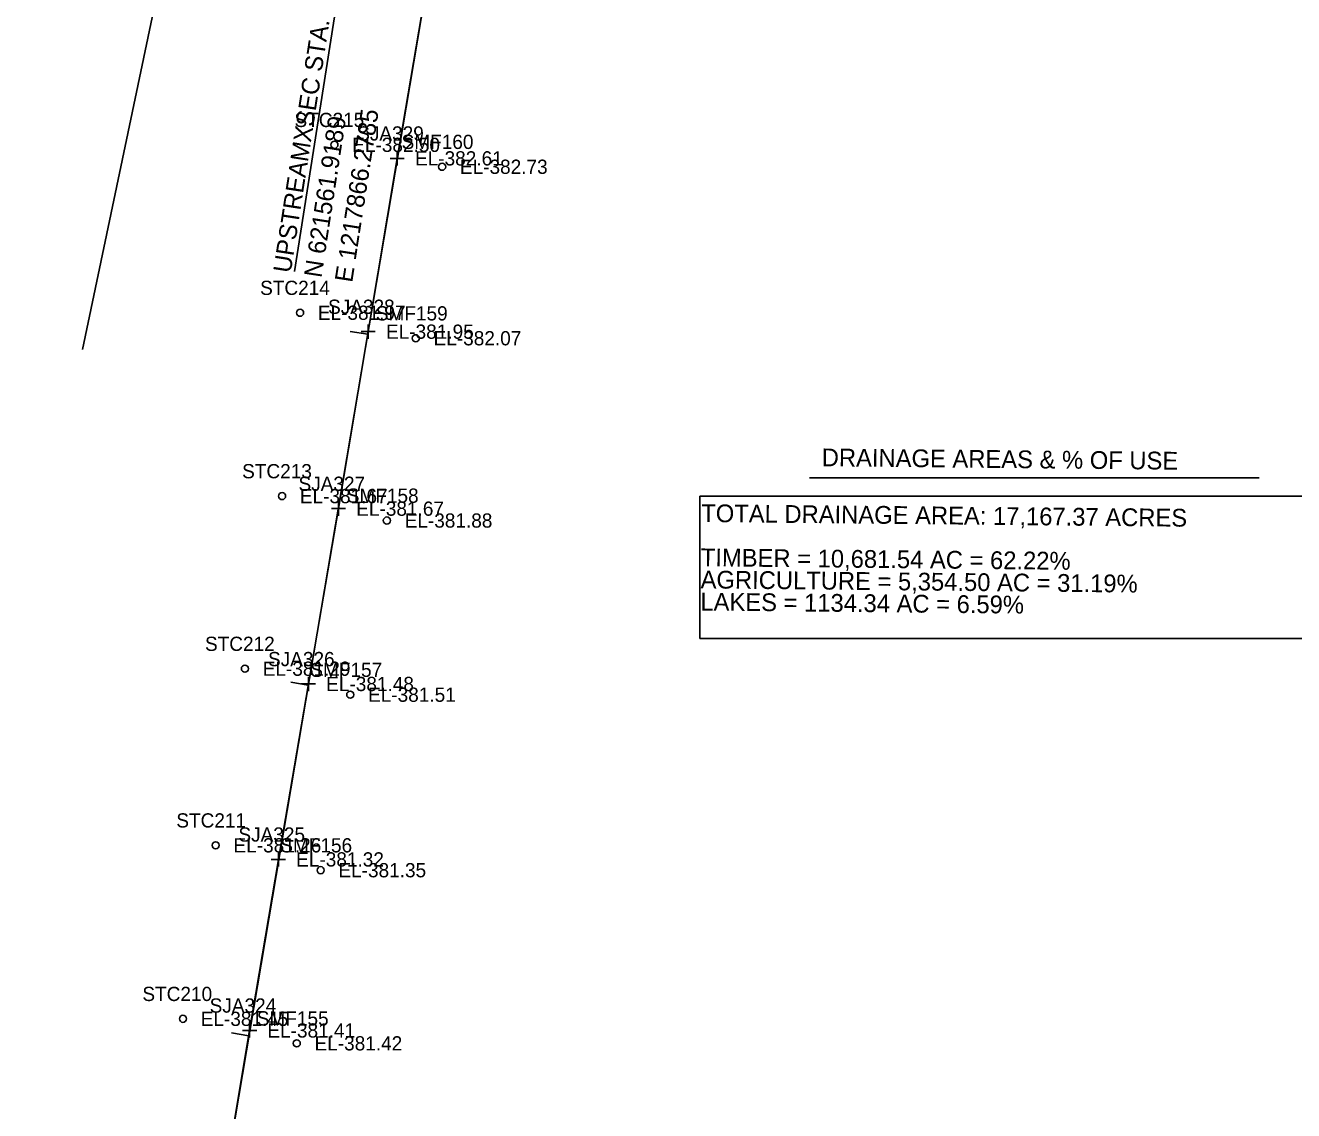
# Model space of a CAD drawing. Extents: x 1189978 to 1314812, y 571533 to 629339.
# Drawn here: x 1217758.6 to 1218115.4, y 621182.5 to 621487.6 of the extents above; entities that cross this region are included whole.
import ezdxf

# ---------------------------------------------------------------- set-up
doc = ezdxf.new("R2010")
doc.units = 0
for name, color, linetype in [('SURVEY - DRAINAGE - Area Shapes Text', 7, 'Continuous'), ('SURVEY - DRAINAGE - Bridge Hydraulic Data - Points - Elevations', 7, 'Continuous'), ('SURVEY - DRAINAGE - Bridge Hydraulic Data - Points - Numbers', 7, 'Continuous'), ('SURVEY - DRAINAGE - Bridge Hydraulic Data with Text', 7, 'Continuous'), ('SURVEY - DTM - Breaklines', 7, 'Continuous'), ('SURVEY - DTM - Spot Points - Elevations', 7, 'Continuous'), ('SURVEY - DTM - Spot Points - Locators', 7, 'Continuous'), ('SURVEY - DTM - Spot Points - Point Numbers', 7, 'Continuous')]:
    doc.layers.add(name, color=color, linetype=linetype)

msp = doc.modelspace()

# ---------------------------------------------------------------- linework, layer by layer
at = {"layer": 'SURVEY - DRAINAGE - Area Shapes Text'}
for p, q in [((1218105.72, 621360.4), (1217979.18, 621360.4)), ((1217948.4, 621355.24), (1218141.41, 621355.24)), ((1217948.4, 621355.24), (1217948.4, 621315.24)), ((1217948.4, 621315.24), (1218141.41, 621315.24))]:
    msp.add_line(p, q, dxfattribs=at)
at = {"layer": 'SURVEY - DRAINAGE - Bridge Hydraulic Data with Text'}
for p, q in [((1217654.48, 620217.59), (1218104.66, 622874.85)), ((1217654.48, 620217.59), (1218104.66, 622874.85)), ((1217654.48, 620217.59), (1218104.66, 622874.85)), ((1217774.74, 621396.44), (1217805.16, 621541.53)), ((1217854.93, 621400.73), (1217850, 621401.56)), ((1217838.22, 621302.13), (1217833.29, 621302.97)), ((1217821.52, 621203.54), (1217816.59, 621204.37))]:
    msp.add_line(p, q, dxfattribs=at)
msp.add_lwpolyline([(1217866.28, 621561.92), (1217853.48, 621540.24), (1217834.35, 621418.36)], dxfattribs=at)
at = {"layer": 'SURVEY - DTM - Breaklines'}
for p, q in [((1217863.24, 621452.2), (1217863.24, 621448.2)), ((1217865.24, 621450.2), (1217861.24, 621450.2)), ((1217855.08, 621403.48), (1217855.08, 621399.48)), ((1217857.08, 621401.48), (1217853.08, 621401.48)), ((1217846.71, 621353.72), (1217846.71, 621349.72)), ((1217848.71, 621351.72), (1217844.71, 621351.72)), ((1217840.25, 621302.43), (1217836.25, 621302.43)), ((1217838.25, 621304.43), (1217838.25, 621300.43)), ((1217831.81, 621253.11), (1217827.81, 621253.11)), ((1217829.81, 621255.11), (1217829.81, 621251.11)), ((1217821.71, 621207.02), (1217821.71, 621203.02)), ((1217823.71, 621205.02), (1217819.71, 621205.02))]:
    msp.add_line(p, q, dxfattribs=at)
msp.add_lwpolyline([(1217813.24, 621154.6), (1217821.71, 621205.02), (1217829.81, 621253.11), (1217838.25, 621302.43), (1217846.71, 621351.72), (1217855.08, 621401.48), (1217863.24, 621450.2), (1217871.68, 621499.81), (1217880.02, 621548.86)], dxfattribs=at)
at = {"layer": 'SURVEY - DTM - Spot Points - Locators'}
for centre in [(1217845.58, 621454.01), (1217875.88, 621447.84), (1217835.91, 621406.8), (1217868.47, 621399.63), (1217830.85, 621355.25), (1217860.33, 621348.38), (1217820.4, 621306.72), (1217850.03, 621299.41), (1217812.18, 621257.07), (1217841.69, 621250.07), (1217802.96, 621208.29), (1217834.97, 621201.4)]:
    msp.add_circle(centre, 1, dxfattribs=at)

# ---------------------------------------------------------------- texts
at = {"layer": 'SURVEY - DRAINAGE - Area Shapes Text'}
for s, p in [('DRAINAGE AREAS & % OF USE', (1217982.65, 621363.64)), ('TOTAL DRAINAGE AREA: 17,167.37 ACRES', (1217948.75, 621347.96)), ('TIMBER = 10,681.54 AC = 62.22%', (1217948.63, 621335.53)), ('AGRICULTURE = 5,354.50 AC = 31.19% ', (1217948.57, 621329.31)), ('LAKES = 1134.34 AC = 6.59%', (1217948.51, 621323.09))]:
    msp.add_text(s, height=4.998, rotation=359.4489, dxfattribs=at).set_placement(p)
at = {"layer": 'SURVEY - DRAINAGE - Bridge Hydraulic Data - Points - Elevations'}
for s, p in [('EL-382.61', (1217868.24, 621448.2)), ('EL-381.95', (1217860.08, 621399.48)), ('EL-381.67', (1217851.71, 621349.72)), ('EL-381.48', (1217843.25, 621300.43)), ('EL-381.32', (1217834.81, 621251.11)), ('EL-381.41', (1217826.71, 621203.02))]:
    msp.add_text(s, height=4, dxfattribs=at).set_placement(p)
at = {"layer": 'SURVEY - DRAINAGE - Bridge Hydraulic Data - Points - Numbers'}
for s, p in [('SJA329', (1217851.98, 621455.2)), ('SJA328', (1217843.79, 621406.48)), ('SJA327', (1217835.47, 621356.72)), ('SJA326', (1217826.9, 621307.43)), ('SJA325', (1217818.57, 621258.11)), ('SJA324', (1217810.47, 621210.02))]:
    msp.add_text(s, height=4, dxfattribs=at).set_placement(p)
at = {"layer": 'SURVEY - DRAINAGE - Bridge Hydraulic Data with Text'}
for s, p in [('UPSTREAMXSEC STA. 11+38.99', (1217833.27, 621417.8)), ('E 1217866.2785', (1217850.57, 621415.13)), ('N 621561.9189', (1217841.92, 621416.46))]:
    msp.add_text(s, height=5, rotation=81.2249, dxfattribs=at).set_placement(p)
at = {"layer": 'SURVEY - DTM - Spot Points - Elevations'}
for s, p in [('EL-382.50', (1217850.58, 621452.01)), ('EL-382.73', (1217880.88, 621445.84)), ('EL-381.97', (1217840.91, 621404.8)), ('EL-382.07', (1217873.47, 621397.63)), ('EL-381.67', (1217835.85, 621353.25)), ('EL-381.88', (1217865.33, 621346.38)), ('EL-381.29', (1217825.4, 621304.72)), ('EL-381.51', (1217855.03, 621297.41)), ('EL-381.26', (1217817.18, 621255.07)), ('EL-381.35', (1217846.69, 621248.07)), ('EL-381.45', (1217807.96, 621206.29)), ('EL-381.42', (1217839.97, 621199.4))]:
    msp.add_text(s, height=4, dxfattribs=at).set_placement(p)
at = {"layer": 'SURVEY - DTM - Spot Points - Point Numbers'}
for s, p in [('STC215', (1217834.34, 621459.01)), ('SMF160', (1217864.47, 621452.84)), ('STC214', (1217824.67, 621411.8)), ('SMF159', (1217857.22, 621404.63)), ('STC213', (1217819.61, 621360.25)), ('SMF158', (1217849.05, 621353.38)), ('STC212', (1217809.16, 621311.72)), ('SMF157', (1217838.79, 621304.41)), ('STC211', (1217801.1, 621262.07)), ('SMF156', (1217830.34, 621255.07)), ('STC210', (1217791.55, 621213.29)), ('SMF155', (1217823.73, 621206.4))]:
    msp.add_text(s, height=4, dxfattribs=at).set_placement(p)

doc.saveas('drawing.dxf')
